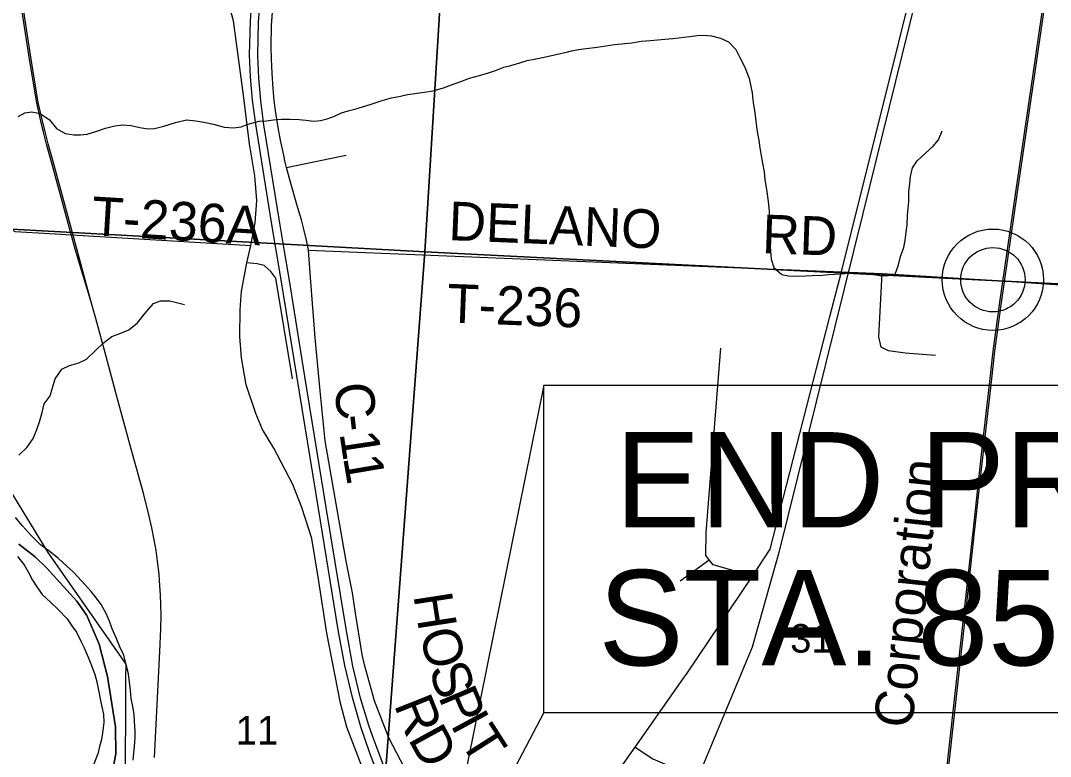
# Model space of a CAD drawing. Extents: x 0 to 34, y 0 to 22.
# Drawn here: x 5.16 to 6.672, y 18.72 to 19.8 of the extents above; entities that cross this region are included whole.
import ezdxf

# ---------------------------------------------------------------- set-up
doc = ezdxf.new("R2010")
doc.units = 0
for name, color, linetype in [('GM_X_Corporation', 7, 'Continuous'), ('GM_X_County_Road', 7, 'Continuous'), ('GM_X_County_Road_Text', 7, 'Continuous'), ('GM_X_Major_River', 7, 'Continuous'), ('GM_X_Minor_River', 7, 'Continuous'), ('GM_X_Rail_Line', 7, 'Continuous'), ('GM_X_Rail_Line_Text', 7, 'Continuous'), ('GM_X_Section_Text', 7, 'Continuous'), ('GM_X_State_Route', 7, 'Continuous'), ('GM_X_Township_Road', 7, 'Continuous'), ('GM_X_Township_Road_Text', 7, 'Continuous'), ('GM_X_Unincorporated', 7, 'Continuous'), ('GM_X_Unincorporated_Location', 7, 'Continuous'), ('GM_X_US_Route', 7, 'Continuous'), ('SH_Data', 7, 'Continuous'), ('SH_Text', 7, 'Continuous')]:
    doc.layers.add(name, color=color, linetype=linetype)

msp = doc.modelspace()

# ---------------------------------------------------------------- linework, layer by layer
at = {"layer": 'GM_X_Corporation'}
for points in [[(4.8161, 20.4698), (5.8125, 20.4147), (5.7537, 19.4608), (5.102, 19.4969), (4.7709, 19.8114)], [(5.8125, 20.4147), (5.8133, 20.4283), (6.802, 20.3679), (6.741, 19.4109), (5.7537, 19.4608)], [(5.102, 19.4969), (5.7537, 19.4608), (5.6796, 18.4816), (5.1903, 18.5084), (5.3139, 18.6644), (5.3147, 18.8352), (5.3148, 18.8557), (5.2004, 19.0195), (5.1234, 19.1449)], [(5.7537, 19.4608), (6.741, 19.4109), (6.6744, 18.4075), (5.6796, 18.4816)]]:
    msp.add_lwpolyline(points, close=True, dxfattribs=at)
for points in [[(5.1284, 18.4671), (5.1903, 18.5127), (5.2233, 18.5561), (5.2341, 18.5742), (5.2632, 18.612), (5.274, 18.6324), (5.2827, 18.6681), (5.2966, 18.706), (5.2998, 18.7242), (5.2994, 18.7637), (5.2878, 18.8376), (5.2753, 18.8848), (5.2574, 18.9268), (5.2423, 18.9482), (5.1987, 18.9964), (5.1813, 19.0133), (5.1572, 19.0317)], [(5.1572, 19.0317), (5.1813, 19.0133), (5.1987, 18.9964), (5.2423, 18.9482), (5.2574, 18.9268), (5.2753, 18.8848), (5.2878, 18.8376), (5.2994, 18.7637), (5.2998, 18.7242), (5.2966, 18.706)]]:
    msp.add_lwpolyline(points, dxfattribs=at)
at = {"layer": 'GM_X_County_Road'}
for points in [[(5.4979, 19.4701), (5.5046, 19.5035), (5.5068, 19.5361), (5.5041, 19.5725), (5.4963, 19.6196), (5.4871, 19.6909), (5.4727, 19.8002), (5.4613, 19.8409), (5.4473, 19.8677), (5.4361, 19.8848), (5.3856, 19.9428), (5.3751, 19.9612), (5.3678, 19.9806), (5.3598, 20.0131)], [(5.5859, 19.4235), (5.5828, 19.4634), (5.58, 19.4783), (5.5756, 19.4961), (5.5723, 19.508), (5.5667, 19.5271), (5.5563, 19.563), (5.5506, 19.5849), (5.5486, 19.5925), (5.5463, 19.6028), (5.5415, 19.6248), (5.5382, 19.6433), (5.5344, 19.6683), (5.5325, 19.683), (5.5307, 19.7008), (5.5292, 19.7232), (5.5282, 19.7439), (5.528, 19.7623), (5.5283, 19.7934), (5.5307, 19.8259)], [(5.6617, 18.7042), (5.639, 18.7631), (5.6298, 18.7984), (5.6096, 18.901), (5.5976, 18.9804), (5.5875, 19.0401), (5.5731, 19.0858), (5.5596, 19.1196), (5.5317, 19.1728), (5.5152, 19.2003), (5.5055, 19.2235), (5.4912, 19.2658), (5.4844, 19.3055), (5.4819, 19.3368), (5.4823, 19.3757), (5.4844, 19.4031), (5.4924, 19.445), (5.4979, 19.4701)], [(5.9262, 18.4961), (5.8955, 18.5075), (5.88, 18.5146), (5.8674, 18.5218), (5.856, 18.5306), (5.8476, 18.5377), (5.8303, 18.5574), (5.819, 18.5718), (5.7789, 18.6233), (5.7531, 18.6558), (5.7289, 18.6929), (5.7009, 18.7474), (5.6797, 18.8019), (5.665, 18.8545), (5.6615, 18.8696), (5.6517, 18.9306), (5.6472, 18.9601), (5.6381, 19.0066), (5.6073, 19.1833), (5.5997, 19.2569), (5.5926, 19.3346), (5.5859, 19.4235)], [(6.0624, 18.7337), (6.0886, 18.7166), (6.1493, 18.6908), (6.1843, 18.6767), (6.3035, 18.6666), (6.4133, 18.6616)]]:
    msp.add_lwpolyline(points, dxfattribs=at)
at = {"layer": 'GM_X_Major_River'}
for points in [[(5.3252, 18.7147), (5.3264, 18.7253), (5.3272, 18.7348), (5.328, 18.7477), (5.328, 18.7572), (5.3272, 18.7717), (5.3265, 18.7823), (5.3246, 18.7933), (5.3224, 18.8051), (5.3212, 18.8169), (5.3182, 18.8412), (5.3152, 18.8545), (5.3118, 18.8686), (5.3058, 18.8812), (5.3005, 18.8945), (5.2944, 18.9074), (5.2907, 18.9188), (5.2857, 18.9298), (5.2785, 18.9432), (5.2713, 18.9527), (5.2638, 18.9622), (5.2494, 18.9778), (5.2376, 18.9907), (5.2277, 18.9995), (5.2156, 19.0105), (5.2012, 19.0219), (5.1891, 19.0307), (5.1762, 19.044), (5.1629, 19.0585), (5.1523, 19.0711)], [(5.1556, 19.0137), (5.1651, 19.0015), (5.1711, 18.9912), (5.1772, 18.9787), (5.1836, 18.9692), (5.1916, 18.9581), (5.2037, 18.9467), (5.2151, 18.9357), (5.2284, 18.922), (5.2352, 18.9121), (5.242, 18.9026), (5.2484, 18.8896), (5.2534, 18.8794), (5.2594, 18.866), (5.2643, 18.8535), (5.2689, 18.8402), (5.2719, 18.8299), (5.2745, 18.8174), (5.2775, 18.8025), (5.2794, 18.793), (5.2817, 18.782), (5.282, 18.7699), (5.2809, 18.7581), (5.2786, 18.7448), (5.2759, 18.7349), (5.2732, 18.7239), (5.2671, 18.7079)]]:
    msp.add_lwpolyline(points, dxfattribs=at)
at = {"layer": 'GM_X_Minor_River'}
for points in [[(5.1563, 19.6597), (5.1662, 19.665), (5.1765, 19.6665), (5.1886, 19.6642), (5.2026, 19.6547), (5.2125, 19.6421), (5.2254, 19.6345), (5.2383, 19.6326), (5.2478, 19.6329), (5.2577, 19.6337), (5.2717, 19.6382), (5.2847, 19.6427), (5.2983, 19.6461), (5.3101, 19.6476), (5.3223, 19.6465), (5.3352, 19.6434), (5.3466, 19.6415), (5.3568, 19.6422), (5.3705, 19.6456), (5.3872, 19.6509), (5.4036, 19.6547), (5.4172, 19.6535), (5.429, 19.6512), (5.4434, 19.6485), (5.459, 19.644), (5.4727, 19.6432), (5.4841, 19.6443), (5.4939, 19.6485), (5.5103, 19.6526), (5.5209, 19.6533), (5.5315, 19.6545), (5.5437, 19.6556), (5.5551, 19.6556), (5.5688, 19.6552), (5.5786, 19.654), (5.59, 19.6528), (5.6003, 19.6536), (5.6102, 19.6562), (5.6208, 19.66), (5.6311, 19.6649), (5.6409, 19.668), (5.6508, 19.6706), (5.6618, 19.674), (5.6732, 19.6774), (5.6907, 19.6831), (5.7048, 19.6872), (5.7177, 19.6895), (5.7283, 19.6917), (5.7424, 19.694), (5.7527, 19.6955), (5.7656, 19.6974), (5.7808, 19.7019), (5.7929, 19.7061), (5.8062, 19.711), (5.8192, 19.7159), (5.834, 19.7197), (5.8473, 19.7238), (5.8575, 19.7272), (5.8697, 19.7322), (5.88, 19.7344), (5.8933, 19.7386), (5.9039, 19.7416), (5.9141, 19.7439), (5.9263, 19.7461), (5.9377, 19.7488), (5.9502, 19.7518), (5.9597, 19.7537), (5.9692, 19.7559), (5.9791, 19.7582), (5.9905, 19.7593), (6.0065, 19.7612), (6.0194, 19.7634), (6.0319, 19.7653), (6.0471, 19.7668), (6.0578, 19.7679), (6.0714, 19.7702), (6.0851, 19.7713), (6.0954, 19.772), (6.106, 19.7732), (6.1178, 19.7739), (6.1428, 19.7769), (6.1535, 19.7784), (6.163, 19.7788), (6.1747, 19.778), (6.188, 19.7745), (6.1994, 19.7692), (6.2104, 19.7578), (6.2161, 19.746), (6.2233, 19.7319), (6.2297, 19.7156), (6.2342, 19.6943), (6.2357, 19.6795), (6.2376, 19.6684), (6.2391, 19.6574)], [(6.2391, 19.6574), (6.2406, 19.6445), (6.2421, 19.6346), (6.244, 19.6251), (6.2455, 19.6137), (6.2474, 19.6019), (6.2496, 19.5913), (6.2519, 19.5783), (6.253, 19.5669), (6.2556, 19.5491), (6.2579, 19.535), (6.2594, 19.5206), (6.2598, 19.5111), (6.2597, 19.5004), (6.2601, 19.4871), (6.2604, 19.4742), (6.2612, 19.462), (6.2623, 19.4503), (6.2661, 19.4377), (6.2778, 19.4278), (6.2877, 19.4255), (6.301, 19.4251), (6.3128, 19.4255), (6.323, 19.4262), (6.3371, 19.4269), (6.347, 19.4277), (6.3648, 19.4288), (6.3762, 19.4295), (6.3979, 19.4295), (6.41, 19.4283), (6.4218, 19.4264), (6.4313, 19.4256), (6.4442, 19.4283), (6.4492, 19.442), (6.4522, 19.4541), (6.4568, 19.4674), (6.4587, 19.478), (6.4602, 19.4898), (6.4618, 19.5008), (6.4626, 19.5149), (6.4641, 19.5347), (6.4645, 19.5495), (6.4657, 19.5609), (6.4668, 19.5715), (6.4699, 19.5844), (6.4768, 19.5947), (6.4882, 19.6053), (6.5, 19.6159), (6.5079, 19.6254), (6.5133, 19.6387)], [(5.1574, 19.1626), (5.1695, 19.174), (5.1783, 19.1869), (5.184, 19.2002), (5.1875, 19.2112), (5.1917, 19.2253), (5.1947, 19.2378), (5.2035, 19.2496), (5.2069, 19.2613), (5.2107, 19.2743), (5.2203, 19.2887), (5.2317, 19.294), (5.2453, 19.2981), (5.2567, 19.3034), (5.2701, 19.316), (5.2811, 19.327), (5.294, 19.3368), (5.3058, 19.341), (5.3191, 19.3463), (5.3317, 19.3569), (5.3427, 19.3709), (5.3552, 19.385), (5.3655, 19.3891), (5.3792, 19.3891), (5.3887, 19.3864), (5.4008, 19.3834)]]:
    msp.add_lwpolyline(points, dxfattribs=at)
at = {"layer": 'GM_X_Rail_Line'}
for points in [[(7.3406, 20.9), (7.1679, 20.8267), (6.9443, 20.7584), (6.8957, 20.7301), (6.8223, 20.6784), (6.7693, 20.6363), (6.6967, 20.5618), (6.6506, 20.4948), (6.6233, 20.4356), (6.5795, 20.2572), (6.397, 19.5172), (6.2733, 19.0197), (6.2341, 18.8804), (6.1559, 18.6926), (6.1001, 18.5873), (6.0785, 18.5248), (6.0655, 18.461), (6.0434, 18.3203), (5.9617, 17.9036), (5.9172, 17.7944), (5.7728, 17.4608), (5.628, 17.1574), (5.5662, 17.0504)], [(6.5178, 18.6795), (6.5316, 18.8035), (6.5433, 18.9091), (6.5587, 19.0497), (6.5727, 19.1769), (6.5822, 19.2617), (6.5884, 19.3152), (6.5974, 19.3834), (6.6216, 19.5486), (6.6468, 19.722), (6.6677, 19.8639)], [(6.5202, 18.6792), (6.534, 18.8033), (6.5456, 18.9089), (6.561, 19.0494), (6.5751, 19.1766), (6.5846, 19.2614), (6.5908, 19.3149), (6.5998, 19.3831), (6.624, 19.5483), (6.6492, 19.7217), (6.6701, 19.8635)], [(5.2642, 19.3855), (5.2403, 19.4647), (5.2274, 19.5116), (5.2058, 19.5909), (5.1981, 19.6188), (5.1935, 19.6364), (5.1896, 19.6529), (5.1836, 19.6796), (5.1731, 19.7437), (5.1614, 19.8198)], [(5.3566, 18.7184), (5.3646, 18.874), (5.3658, 18.9074), (5.3662, 18.9276), (5.3659, 18.9431), (5.3654, 18.9574), (5.3646, 18.9708), (5.3633, 18.9879), (5.3611, 19.0067), (5.3588, 19.0226), (5.3562, 19.0383), (5.3528, 19.0557), (5.3485, 19.0749), (5.3409, 19.1046), (5.3219, 19.1732), (5.3014, 19.2486), (5.2856, 19.3071), (5.2702, 19.3633), (5.2623, 19.3926), (5.2426, 19.4653), (5.2297, 19.5122), (5.2081, 19.5915), (5.2004, 19.6194), (5.1958, 19.637), (5.1919, 19.6534), (5.186, 19.6801), (5.1755, 19.744), (5.1638, 19.8202)]]:
    msp.add_lwpolyline(points, dxfattribs=at)
at = {"layer": 'GM_X_State_Route'}
for points in [[(6.3653, 19.4317), (6.534, 20.1063), (6.5464, 20.1759), (6.5487, 20.1966)], [(6.3479, 19.3639), (6.3484, 19.3658), (6.3653, 19.4317)], [(6.1326, 18.8335), (6.139, 18.8426), (6.2346, 18.9846), (6.2608, 19.0242), (6.3479, 19.3639)], [(5.9777, 18.6126), (5.9819, 18.6193), (6.0624, 18.7337), (6.1326, 18.8335)]]:
    msp.add_lwpolyline(points, dxfattribs=at)
at = {"layer": 'GM_X_Township_Road'}
for p, q in [((5.5506, 19.5849), (5.6284, 19.6009)), ((5.6284, 19.6009), (5.6382, 19.6029)), ((6.5035, 19.3089), (6.459, 19.3122)), ((6.1285, 18.9779), (6.1713, 19.0086))]:
    msp.add_line(p, q, dxfattribs=at)
for points in [[(5.0969, 19.5282), (5.1057, 19.5228), (5.1208, 19.5094), (5.1358, 19.4998), (5.1521, 19.491), (5.2023, 19.4881), (5.4979, 19.4701)], [(5.5828, 19.4634), (6.1569, 19.4398), (6.3653, 19.4317)], [(5.5592, 19.2747), (5.5347, 19.4222), (5.5275, 19.4319), (5.5174, 19.4407), (5.5072, 19.4433), (5.4924, 19.445)], [(6.3653, 19.4317), (6.4253, 19.4291), (6.6014, 19.4184), (6.9352, 19.3955), (7.3304, 19.3689)], [(6.5035, 19.3089), (6.459, 19.3122), (6.4343, 19.3155), (6.4236, 19.3212), (6.4203, 19.3361), (6.4253, 19.4291)], [(6.2346, 18.9846), (6.1768, 19.0014), (6.1713, 19.0086), (6.1662, 19.0153), (6.1666, 19.0487), (6.1881, 19.3196)]]:
    msp.add_lwpolyline(points, dxfattribs=at)
at = {"layer": 'GM_X_Unincorporated'}
for radius in [0.0744, 0.0472]:
    msp.add_circle((6.5878, 19.42), radius, dxfattribs=at)
at = {"layer": 'GM_X_Unincorporated_Location'}
msp.add_line((6.5878, 19.42), (6.5878, 19.42), dxfattribs=at)
at = {"layer": 'GM_X_US_Route'}
for points in [[(5.5469, 19.4647), (5.5405, 19.5029), (5.5173, 19.6474), (5.5126, 19.6824), (5.5097, 19.7166), (5.5081, 19.7488), (5.5095, 19.7982), (5.5121, 19.8364), (5.5142, 19.8625), (5.5184, 19.9064)], [(5.8082, 18.2251), (5.8054, 18.2721), (5.8025, 18.3106), (5.7996, 18.3432), (5.7922, 18.3857), (5.779, 18.4406), (5.769, 18.4733), (5.7514, 18.5212), (5.7037, 18.6446), (5.6727, 18.7251), (5.6595, 18.7638), (5.6472, 18.8068), (5.6359, 18.8538), (5.6264, 18.9059), (5.5972, 19.0841), (5.5656, 19.2791), (5.5422, 19.4228), (5.5285, 19.5041), (5.5053, 19.6486), (5.5006, 19.6836), (5.4977, 19.7179), (5.4961, 19.75), (5.4974, 19.7994), (5.5001, 19.8376)], [(5.6219, 19.0055), (5.6092, 19.0829), (5.5776, 19.2779), (5.5542, 19.4216), (5.5469, 19.4647)], [(5.6788, 18.7451), (5.6718, 18.7639), (5.6592, 18.8055), (5.6479, 18.8526), (5.6384, 18.9047), (5.6219, 19.0055)], [(5.7594, 18.5322), (5.7153, 18.647), (5.684, 18.731), (5.6788, 18.7451)]]:
    msp.add_lwpolyline(points, dxfattribs=at)
at = {"layer": 'SH_Data'}
msp.add_lwpolyline([(5.9283, 19.265), (5.7703, 18.4834), (5.9283, 18.784)], close=True, dxfattribs=at)
at = {"layer": 'SH_Text'}
for p, q in [((5.945, 19.265), (6.3343, 19.265)), ((6.3152, 19.265), (6.3343, 19.265)), ((6.3343, 19.265), (6.7313, 19.265)), ((6.3343, 19.265), (6.7313, 19.265))]:
    msp.add_line(p, q, dxfattribs=at)
msp.add_lwpolyline([(6.6994, 18.784), (5.9283, 18.784), (5.9283, 19.265), (5.945, 19.265)], dxfattribs=at)

# ---------------------------------------------------------------- texts
at = {"layer": 'GM_X_County_Road_Text'}
for s, rotation, p in [('C', 275.7686, (5.6205, 19.2667)), ('-', 276.4183, (5.6252, 19.2199)), ('1', 278.5573, (5.6281, 19.1946)), ('1', 279.6447, (5.6334, 19.1591)), ('H', 278.8431, (5.7367, 18.9567)), ('O', 283.9233, (5.7455, 18.9019)), ('S', 288.5414, (5.7589, 18.8486)), ('P', 292.8643, (5.7727, 18.8079)), ('R', 291.663, (5.7078, 18.7961)), ('I', 298.5013, (5.7903, 18.767)), ('D', 298.746, (5.7282, 18.7459)), ('T', 302.5038, (5.8036, 18.7428))]:
    msp.add_text(s, height=0.0568, rotation=rotation, dxfattribs=at).set_placement(p)
at = {"layer": 'GM_X_Rail_Line_Text'}
msp.add_text('Corporation', height=0.056629, rotation=83.824, dxfattribs=at).set_placement((6.4689, 18.7603))
at = {"layer": 'GM_X_Section_Text'}
for s, p in [('31', (6.2901, 18.8726)), ('11', (5.4759, 18.7376))]:
    msp.add_text(s, height=0.04186, rotation=0, dxfattribs=at).set_placement(p)
at = {"layer": 'GM_X_Township_Road_Text'}
for s, rotation, p in [('T-236A', 356.52, (5.2628, 19.4856)), ('DELANO', 357.6627, (5.7877, 19.4782)), ('RD', 358.0261, (6.2484, 19.459)), ('T-236', 357.7544, (5.7854, 19.3573))]:
    msp.add_text(s, height=0.05682, rotation=rotation, dxfattribs=at).set_placement(p)
at = {"layer": 'SH_Text'}
for s, p in [('END PROJECT', (6.0332, 19.0563)), ('STA. 857+55 U.S. 23', (6.0086, 18.8538))]:
    msp.add_text(s, height=0.14, dxfattribs=at).set_placement(p)

doc.saveas('drawing.dxf')
